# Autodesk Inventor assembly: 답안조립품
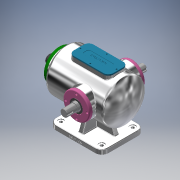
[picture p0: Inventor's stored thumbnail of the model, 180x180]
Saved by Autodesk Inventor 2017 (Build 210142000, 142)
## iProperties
Part Number: 답안조립품
Material: 일반
Document SubType Name: Assembly
Designer: Administrator
Author: Administrator
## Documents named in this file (12)
- C:\Users\Administrator\Desktop\711106V1017\답안조립품.iam
- C:\Users\Administrator\Desktop\711106V1017\본체.ipt
- C:\Users\Administrator\Desktop\711106V1017\베어링 6205.ipt
- 베어링 6205.ipt
- C:\Users\Administrator\Desktop\711106V1017\축 커버.ipt
- C:\Users\Administrator\Desktop\711106V1017\오일실.ipt
- 오일실.ipt
- C:\Users\Administrator\Desktop\711106V1017\슬라이드 커버.ipt
- C:\Users\Administrator\Desktop\711106V1017\부시.ipt
- C:\Users\Administrator\Desktop\711106V1017\슬라이드.ipt
- C:\Users\Administrator\Desktop\711106V1017\편심축.ipt
- C:\Users\Administrator\Desktop\711106V1017\상부커버.ipt
